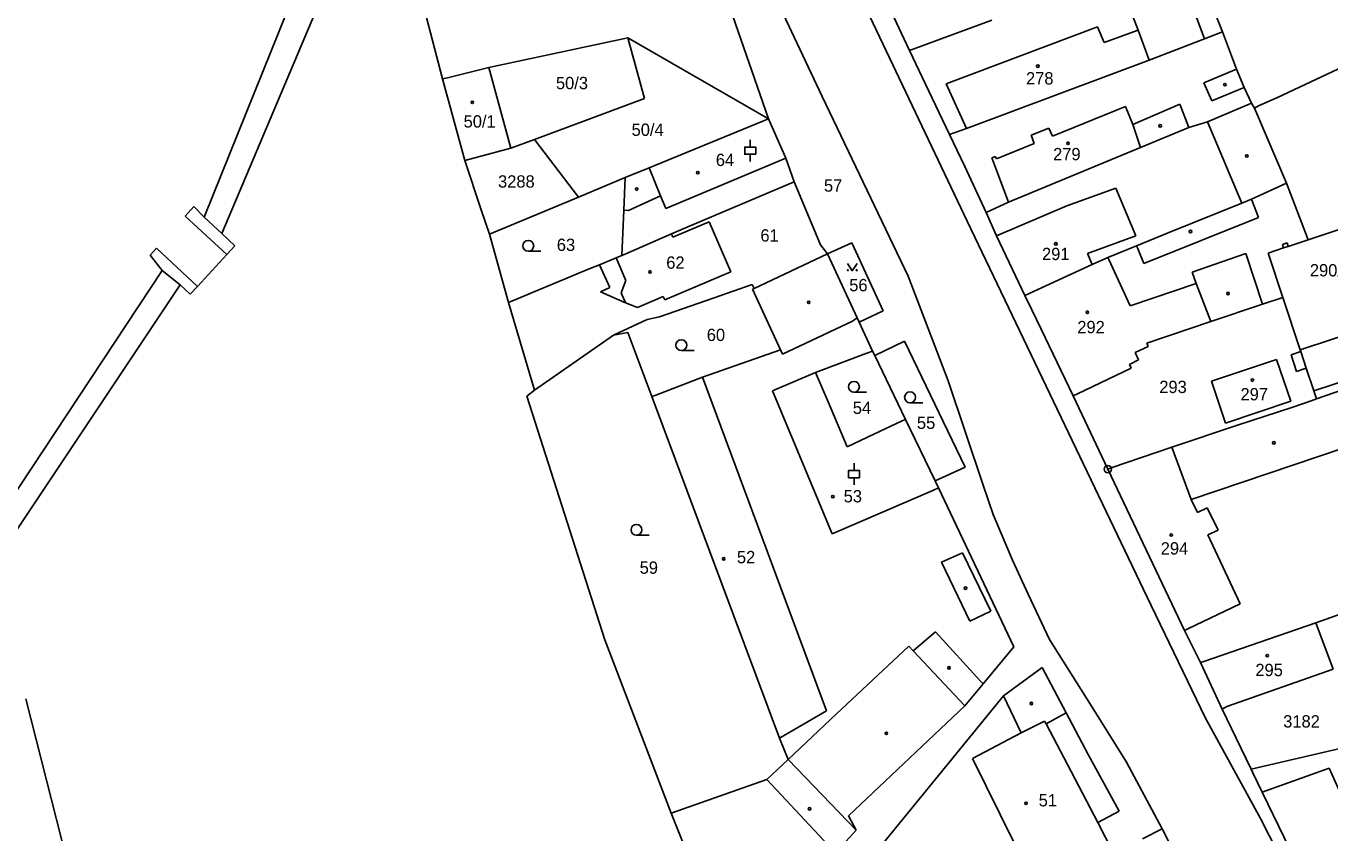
# Model space of a CAD drawing. Extents: x -736345 to -729997, y -1130177 to -1122501.
# Drawn here: x -733843 to -733663.1, y -1126639.6 to -1126528.3 of the extents above; entities that cross this region are included whole.
import ezdxf

# ---------------------------------------------------------------- set-up
doc = ezdxf.new("R2010")
doc.units = 0
for name, color, linetype in [('Vrstva 1', 7, 'Continuous'), ('Vrstva 18', 7, 'Continuous'), ('Vrstva 19', 7, 'Continuous'), ('Vrstva 25', 7, 'Continuous'), ('Vrstva 4', 7, 'Continuous')]:
    doc.layers.add(name, color=color, linetype=linetype)

msp = doc.modelspace()

# ---------------------------------------------------------------- linework, layer by layer
at = {"layer": 'Vrstva 1'}
for points in [[(-733731.42, -1126516.63), (-733713.1, -1126555.17)], [(-733685.1, -1126517.34), (-733680.35, -1126530.03)], [(-733677.89, -1126529.05), (-733682.88, -1126516.53)], [(-733785.51, -1126535.51), (-733789.39, -1126520.69)], [(-733740.8, -1126521.64), (-733733.13, -1126537.99)], [(-733726.49, -1126520.05), (-733721.07, -1126531.61)], [(-733745.84, -1126525.67), (-733740.52, -1126541.04)], [(-733721.07, -1126531.61), (-733709.72, -1126527.43)], [(-733649.04, -1126528.12), (-733670.3, -1126538.13)], [(-733759.93, -1126529.89), (-733779.1, -1126533.95)], [(-733757.61, -1126538.25), (-733759.93, -1126529.89)], [(-733740.52, -1126541.04), (-733759.93, -1126529.89)], [(-733680.35, -1126530.03), (-733688, -1126532.96)], [(-733680.35, -1126530.03), (-733677.89, -1126529.05)], [(-733677.89, -1126529.05), (-733675.94, -1126534.19)], [(-733718.42, -1126537.22), (-733721.07, -1126531.61)], [(-733779.1, -1126533.95), (-733784.81, -1126535.39)], [(-733779.1, -1126533.95), (-733776.08, -1126545.11)], [(-733688, -1126532.96), (-733713.21, -1126542.37)], [(-733675.94, -1126534.19), (-733674.88, -1126536.71)], [(-733784.81, -1126535.39), (-733785.51, -1126535.51)], [(-733785.51, -1126535.51), (-733782.42, -1126546.78)], [(-733733.13, -1126537.99), (-733721.26, -1126562.75)], [(-733715.54, -1126543.2), (-733718.42, -1126537.22)], [(-733674.88, -1126536.71), (-733673.88, -1126538.89)], [(-733772.8, -1126543.89), (-733757.61, -1126538.25)], [(-733673.88, -1126538.89), (-733679.95, -1126541.46)], [(-733673.44, -1126539.59), (-733673.88, -1126538.89)], [(-733672.9, -1126539.26), (-733673.44, -1126539.59)], [(-733673.44, -1126539.59), (-733669.06, -1126549.93)], [(-733670.3, -1126538.13), (-733672.9, -1126539.26)], [(-733756.98, -1126547.8), (-733740.52, -1126541.04)], [(-733740.52, -1126541.04), (-733738.11, -1126546.46)], [(-733679.95, -1126541.46), (-733682.51, -1126542.24)], [(-733713.21, -1126542.37), (-733715.54, -1126543.2)], [(-733713.45, -1126547.64), (-733715.54, -1126543.2)], [(-733682.51, -1126542.24), (-733689.17, -1126545)], [(-733782.42, -1126546.78), (-733776.08, -1126545.11)], [(-733776.08, -1126545.11), (-733772.8, -1126543.89)], [(-733766.76, -1126551.84), (-733772.8, -1126543.89)], [(-733689.17, -1126545), (-733707.42, -1126552.54)], [(-733782.42, -1126546.78), (-733780.15, -1126553.61)], [(-733738.11, -1126546.46), (-733737, -1126549.74)], [(-733760.31, -1126549.16), (-733756.98, -1126547.8)], [(-733710.48, -1126553.96), (-733713.45, -1126547.64)], [(-733766.76, -1126551.84), (-733760.31, -1126549.16)], [(-733760.31, -1126549.16), (-733760.47, -1126553.67)], [(-733751.96, -1126556.08), (-733737, -1126549.74)], [(-733737, -1126549.74), (-733733.33, -1126558.42)], [(-733669.06, -1126549.93), (-733673.87, -1126552.12)], [(-733669.06, -1126549.93), (-733666.06, -1126557.74)], [(-733779.04, -1126556.94), (-733766.76, -1126551.84)], [(-733673.87, -1126552.12), (-733675.22, -1126552.67)], [(-733780.15, -1126553.61), (-733779.04, -1126556.94)], [(-733760.47, -1126553.67), (-733760.76, -1126559.9)], [(-733707.42, -1126552.54), (-733710.48, -1126553.96)], [(-733710.48, -1126553.96), (-733709.04, -1126557.2)], [(-733685.38, -1126556.79), (-733675.22, -1126552.67)], [(-733753.72, -1126557.39), (-733748.7, -1126555.24)], [(-733748.7, -1126555.24), (-733745.7, -1126562.14)], [(-733713.1, -1126555.17), (-733687.72, -1126608.18)], [(-733658.17, -1126555.13), (-733666.06, -1126557.74)], [(-733779.04, -1126556.94), (-733776.4, -1126566.37)], [(-733760.21, -1126559.66), (-733753.91, -1126556.93)], [(-733753.91, -1126556.93), (-733751.96, -1126556.08)], [(-733753.91, -1126556.93), (-733753.72, -1126557.39)], [(-733709.04, -1126557.2), (-733705.15, -1126565.4)], [(-733689.74, -1126558.57), (-733685.38, -1126556.79)], [(-733666.06, -1126557.74), (-733668.8, -1126558.65)], [(-733733.33, -1126558.42), (-733732.36, -1126559.69)], [(-733732.36, -1126559.69), (-733729.04, -1126558.15)], [(-733729.04, -1126558.15), (-733724.69, -1126567.55)], [(-733693.71, -1126560.18), (-733689.74, -1126558.57)], [(-733669.44, -1126558.86), (-733671.56, -1126559.57)], [(-733671.56, -1126559.57), (-733669.54, -1126565.7)], [(-733668.95, -1126558.16), (-733669.6, -1126558.38)], [(-733669.6, -1126558.38), (-733669.44, -1126558.86)], [(-733668.8, -1126558.65), (-733668.95, -1126558.16)], [(-733765.26, -1126561.76), (-733763.84, -1126561.17)], [(-733763.84, -1126561.17), (-733761.87, -1126560.36)], [(-733762.42, -1126564.33), (-733763.84, -1126561.17)], [(-733761.87, -1126560.36), (-733761.56, -1126560.23)], [(-733761.56, -1126560.23), (-733760.76, -1126559.9)], [(-733760.76, -1126559.9), (-733760.21, -1126559.66)], [(-733742.52, -1126564.45), (-733732.36, -1126559.69)], [(-733732.36, -1126559.69), (-733728.28, -1126568.49)], [(-733705.15, -1126565.4), (-733695.84, -1126561.14)], [(-733693.71, -1126560.18), (-733695.84, -1126561.14)], [(-733776.4, -1126566.37), (-733765.26, -1126561.76)], [(-733754.84, -1126566.04), (-733745.7, -1126562.14)], [(-733721.26, -1126562.75), (-733715.75, -1126577.18)], [(-733763.72, -1126564.9), (-733762.42, -1126564.33)], [(-733760.24, -1126566.44), (-733763.72, -1126564.9)], [(-733748, -1126565.74), (-733742.79, -1126563.91)], [(-733742.79, -1126563.91), (-733742.52, -1126564.45)], [(-733742.74, -1126564.57), (-733742.52, -1126564.45)], [(-733738.87, -1126572.91), (-733742.74, -1126564.57)], [(-733776.4, -1126566.37), (-733772.79, -1126578.49)], [(-733758.59, -1126567.1), (-733760.24, -1126566.44)], [(-733758.59, -1126567.1), (-733755.04, -1126565.57)], [(-733755.55, -1126568.38), (-733748, -1126565.74)], [(-733755.04, -1126565.57), (-733754.84, -1126566.04)], [(-733705.15, -1126565.4), (-733704.18, -1126567.42)], [(-733679.48, -1126569), (-733672.35, -1126566.6)], [(-733669.54, -1126565.7), (-733672.35, -1126566.6)], [(-733669.54, -1126565.7), (-733667.16, -1126572.92)], [(-733757.27, -1126568.72), (-733755.55, -1126568.38)], [(-733728.28, -1126568.49), (-733728.01, -1126569.09)], [(-733724.69, -1126567.55), (-733728.01, -1126569.09)], [(-733704.18, -1126567.42), (-733702.91, -1126570.07)], [(-733653.79, -1126568.52), (-733667.16, -1126572.92)], [(-733761.9, -1126570.88), (-733757.27, -1126568.72)], [(-733726.15, -1126573.11), (-733728.01, -1126569.09)], [(-733702.91, -1126570.07), (-733698.49, -1126579.28)], [(-733688.33, -1126571.98), (-733679.48, -1126569)], [(-733772.79, -1126578.49), (-733761.9, -1126570.88)], [(-733761.9, -1126570.88), (-733759.92, -1126570.52)], [(-733759.92, -1126570.52), (-733756.62, -1126579.37)], [(-733721.75, -1126571.72), (-733725.86, -1126573.71)], [(-733713.39, -1126589.09), (-733721.75, -1126571.72)], [(-733688.12, -1126572.45), (-733688.33, -1126571.98)], [(-733749.62, -1126576.71), (-733738.87, -1126572.91)], [(-733734.04, -1126576.05), (-733726.95, -1126573.4)], [(-733726.95, -1126573.4), (-733726.15, -1126573.11)], [(-733726.15, -1126573.11), (-733725.86, -1126573.71)], [(-733725.86, -1126573.71), (-733721.64, -1126582.52)], [(-733689.94, -1126573.3), (-733688.12, -1126572.45)], [(-733689.48, -1126574.3), (-733689.94, -1126573.3)], [(-733667.08, -1126573.16), (-733668.41, -1126573.6)], [(-733668.41, -1126573.6), (-733667.65, -1126575.9)], [(-733667.16, -1126572.92), (-733667.08, -1126573.16)], [(-733697.89, -1126578.99), (-733690.48, -1126575.46)], [(-733690.72, -1126574.93), (-733689.48, -1126574.3)], [(-733690.48, -1126575.46), (-733690.72, -1126574.93)], [(-733679.41, -1126577.26), (-733670.42, -1126574.24)], [(-733670.42, -1126574.24), (-733668.44, -1126579.99)], [(-733667.65, -1126575.9), (-733666.32, -1126575.46)], [(-733666.32, -1126575.46), (-733665.29, -1126578.59)], [(-733651.93, -1126574.22), (-733665.29, -1126578.59)], [(-733756.06, -1126579.16), (-733749.62, -1126576.71)], [(-733739.98, -1126578.59), (-733734.04, -1126576.05)], [(-733734.04, -1126576.05), (-733732.31, -1126580.11)], [(-733715.75, -1126577.18), (-733710.9, -1126591.59)], [(-733677.47, -1126583.02), (-733679.41, -1126577.26)], [(-733772.79, -1126578.49), (-733773.89, -1126579.3)], [(-733773.89, -1126579.3), (-733763.09, -1126612.94)], [(-733756.62, -1126579.37), (-733756.06, -1126579.16)], [(-733739, -1126626.51), (-733756.62, -1126579.37)], [(-733731.75, -1126598.29), (-733739.98, -1126578.59)], [(-733698.49, -1126579.28), (-733697.89, -1126578.99)], [(-733698.49, -1126579.28), (-733693.7, -1126589.38)], [(-733665.29, -1126578.59), (-733664.92, -1126579.68)], [(-733664.92, -1126579.68), (-733658.94, -1126577.63)], [(-733732.31, -1126580.11), (-733729.67, -1126586.28)], [(-733668.44, -1126579.99), (-733677.47, -1126583.02)], [(-733668.18, -1126580.81), (-733675.81, -1126583.3)], [(-733665.62, -1126579.95), (-733668.18, -1126580.81)], [(-733664.92, -1126579.68), (-733665.62, -1126579.95)], [(-733726, -1126584.56), (-733722.09, -1126582.73)], [(-733722.09, -1126582.73), (-733721.64, -1126582.52)], [(-733721.64, -1126582.52), (-733717.54, -1126590.99)], [(-733729.67, -1126586.28), (-733726, -1126584.56)], [(-733675.81, -1126583.3), (-733684.87, -1126586.34)], [(-733684.87, -1126586.34), (-733693.09, -1126589.17)], [(-733717.54, -1126590.99), (-733713.39, -1126589.09)], [(-733693.7, -1126589.38), (-733693.09, -1126589.17)], [(-733683.14, -1126611.63), (-733693.7, -1126589.38)], [(-733717.84, -1126592.3), (-733717.08, -1126591.97)], [(-733717.08, -1126591.97), (-733717.54, -1126590.99)], [(-733717.08, -1126591.97), (-733706.69, -1126613.9)], [(-733710.9, -1126591.59), (-733709.5, -1126595.62)], [(-733717.84, -1126592.3), (-733731.75, -1126598.29)], [(-733709.5, -1126595.62), (-733706.83, -1126601.94)], [(-733706.83, -1126601.94), (-733704.67, -1126606.63)], [(-733649.94, -1126605.24), (-733665.01, -1126610.6)], [(-733704.67, -1126606.63), (-733701.75, -1126612.86)], [(-733687.72, -1126608.18), (-733680.22, -1126623.75)], [(-733680.93, -1126616.06), (-733683.14, -1126611.63)], [(-733665.01, -1126610.6), (-733680.45, -1126615.89)], [(-733665.01, -1126610.6), (-733662.61, -1126616.99)], [(-733763.09, -1126612.94), (-733753.94, -1126636.85)], [(-733701.75, -1126612.86), (-733696.09, -1126621.83)], [(-733706.69, -1126613.9), (-733710.92, -1126618.99)], [(-733708.1, -1126620.64), (-733702.76, -1126616.75)], [(-733699.46, -1126623.01), (-733702.76, -1126616.75)], [(-733680.45, -1126615.89), (-733680.93, -1126616.06)], [(-733680.93, -1126616.06), (-733677.9, -1126622.47)], [(-733662.61, -1126616.99), (-733677.3, -1126622.13)], [(-733717.5, -1126632.15), (-733708.1, -1126620.64)], [(-733710.92, -1126618.99), (-733713.42, -1126622.03)], [(-733823.88, -1126696.34), (-733843.01, -1126621.05)], [(-733713.42, -1126622.03), (-733729.5, -1126637.19)], [(-733691.13, -1126629.82), (-733696.09, -1126621.83)], [(-733677.3, -1126622.13), (-733677.9, -1126622.47)], [(-733677.9, -1126622.47), (-733676.01, -1126626.49)], [(-733699.46, -1126623.01), (-733696.4, -1126628.72)], [(-733680.22, -1126623.75), (-733672.62, -1126637.59)], [(-733737.82, -1126629.44), (-733739, -1126626.51)], [(-733676.01, -1126626.49), (-733673.91, -1126630.78)], [(-733658.87, -1126627.26), (-733673.91, -1126630.78)], [(-733740.75, -1126632.19), (-733737.82, -1126629.44)], [(-733692.12, -1126636.56), (-733696.4, -1126628.72)], [(-733691.13, -1126629.82), (-733686.21, -1126638.98)], [(-733673.91, -1126630.78), (-733673.67, -1126631.27)], [(-733673.67, -1126631.27), (-733672.38, -1126633.95)], [(-733753.94, -1126636.85), (-733740.75, -1126632.19)], [(-733740.75, -1126632.19), (-733731.57, -1126642.03)], [(-733726.5, -1126643.18), (-733717.5, -1126632.15)], [(-733672.38, -1126633.95), (-733665.5, -1126648.15)], [(-733745.44, -1126658.12), (-733753.94, -1126636.85)], [(-733695.1, -1126638.12), (-733692.12, -1126636.56)], [(-733729.5, -1126637.19), (-733728.43, -1126639.17)], [(-733692.99, -1126642.16), (-733695.1, -1126638.12)], [(-733672.62, -1126637.59), (-733664.04, -1126654.46)], [(-733728.43, -1126639.17), (-733731.26, -1126642.3)], [(-733688.91, -1126640.37), (-733686.21, -1126638.98)], [(-733686.21, -1126638.98), (-733681.32, -1126648.5)]]:
    msp.add_lwpolyline(points, dxfattribs=at)
at = {"layer": 'Vrstva 25'}
for points in [[(-733742.29, -1126545.94), (-733743.79, -1126545.94), (-733743.79, -1126544.94), (-733742.29, -1126544.94), (-733742.29, -1126545.94)], [(-733743.04, -1126544.94), (-733743.04, -1126543.94)], [(-733743.04, -1126546.94), (-733743.04, -1126545.94)], [(-733773.67, -1126559.32), (-733771.92, -1126559.32)], [(-733729.63, -1126560.994), (-733728.96, -1126562), (-733728.289, -1126560.994)], [(-733752.55, -1126573.02), (-733750.8, -1126573.02)], [(-733728.73, -1126578.77), (-733726.98, -1126578.77)], [(-733720.99, -1126580.22), (-733719.24, -1126580.22)], [(-733727.97, -1126590.56), (-733729.47, -1126590.56), (-733729.47, -1126589.56), (-733727.97, -1126589.56), (-733727.97, -1126590.56)], [(-733728.72, -1126589.56), (-733728.72, -1126588.56)], [(-733728.72, -1126591.56), (-733728.72, -1126590.56)], [(-733758.74, -1126598.5), (-733756.99, -1126598.5)]]:
    msp.add_lwpolyline(points, dxfattribs=at)
for centre, radius in [((-733703.36, -1126533.79), 0.175), ((-733677.54, -1126536.34), 0.175), ((-733781.39, -1126538.78), 0.175), ((-733686.48, -1126542.01), 0.175), ((-733699.2, -1126544.42), 0.175), ((-733674.51, -1126546.18), 0.175), ((-733750.27, -1126548.48), 0.175), ((-733758.7, -1126550.74), 0.175), ((-733682.29, -1126556.6), 0.175), ((-733773.67, -1126558.57), 0.75), ((-733700.88, -1126558.3), 0.175), ((-733756.87, -1126562.17), 0.175), ((-733729.563, -1126561.933), 0.067), ((-733728.356, -1126561.933), 0.067), ((-733677.11, -1126565.14), 0.175), ((-733734.97, -1126566.36), 0.175), ((-733696.52, -1126567.73), 0.175), ((-733752.55, -1126572.27), 0.75), ((-733728.73, -1126578.02), 0.75), ((-733673.75, -1126577.09), 0.175), ((-733720.99, -1126579.47), 0.75), ((-733670.8, -1126585.74), 0.175), ((-733693.7, -1126589.38), 0.5), ((-733693.7, -1126589.38), 0.032), ((-733731.65, -1126593.18), 0.175), ((-733758.74, -1126597.75), 0.75), ((-733684.95, -1126598.46), 0.175), ((-733746.7, -1126601.75), 0.175), ((-733713.34, -1126605.8), 0.175), ((-733671.7, -1126615.1), 0.175), ((-733715.61, -1126616.78), 0.175), ((-733704.25, -1126621.71), 0.175), ((-733724.26, -1126625.82), 0.175), ((-733734.85, -1126636.23), 0.175), ((-733704.98, -1126635.48), 0.175)]:
    msp.add_circle(centre, radius, dxfattribs=at)
at = {"layer": 'Vrstva 4'}
for points in [[(-733818.4, -1126554.6), (-733805.63, -1126522.96)], [(-733802.11, -1126524.09), (-733815.96, -1126556.86)], [(-733691.3, -1126524.14), (-733689.52, -1126528.8)], [(-733695.12, -1126528.37), (-733716, -1126536.23)], [(-733694.21, -1126530.51), (-733695.12, -1126528.37)], [(-733689.52, -1126528.8), (-733694.21, -1126530.51)], [(-733689.52, -1126528.8), (-733688, -1126532.96)], [(-733675.94, -1126534.19), (-733680.43, -1126536.08)], [(-733680.43, -1126536.08), (-733679.33, -1126538.58)], [(-733716, -1126536.23), (-733713.21, -1126542.37)], [(-733679.33, -1126538.58), (-733674.88, -1126536.71)], [(-733701.35, -1126543.44), (-733691.27, -1126539.35)], [(-733691.27, -1126539.35), (-733690.26, -1126541.83)], [(-733690.26, -1126541.83), (-733683.77, -1126539.03)], [(-733683.77, -1126539.03), (-733682.51, -1126542.24)], [(-733679.95, -1126541.46), (-733675.22, -1126552.67)], [(-733704.27, -1126543.32), (-733701.84, -1126542.34)], [(-733703.85, -1126544.46), (-733704.27, -1126543.32)], [(-733701.84, -1126542.34), (-733701.35, -1126543.44)], [(-733690.26, -1126541.83), (-733689.17, -1126545)], [(-733709.06, -1126546.57), (-733703.85, -1126544.46)], [(-733754.67, -1126553.41), (-733738.11, -1126546.46)], [(-733709.7, -1126546.43), (-733709.25, -1126546.24)], [(-733707.42, -1126552.54), (-733709.7, -1126546.43)], [(-733709.25, -1126546.24), (-733709.06, -1126546.57)], [(-733755.44, -1126551.67), (-733756.98, -1126547.8)], [(-733699.35, -1126553.07), (-733692.6, -1126550.6)], [(-733692.6, -1126550.6), (-733689.85, -1126557.19)], [(-733759.86, -1126553.69), (-733755.44, -1126551.67)], [(-733755.44, -1126551.67), (-733754.67, -1126553.41)], [(-733672.91, -1126554.66), (-733673.87, -1126552.12)], [(-733821.01, -1126554.48), (-733819.8, -1126553.14)], [(-733819.8, -1126553.14), (-733818.4, -1126554.6)], [(-733759.86, -1126553.69), (-733760.47, -1126553.67)], [(-733709.04, -1126557.2), (-733699.35, -1126553.07)], [(-733815.28, -1126559.78), (-733821.01, -1126554.48)], [(-733818.4, -1126554.6), (-733815.96, -1126556.86)], [(-733688.75, -1126560.99), (-733672.91, -1126554.66)], [(-733815.96, -1126556.86), (-733814.15, -1126558.55)], [(-733689.85, -1126557.19), (-733696.51, -1126559.63)], [(-733824.95, -1126558.87), (-733825.85, -1126559.88)], [(-733819.33, -1126564.16), (-733824.95, -1126558.87)], [(-733814.15, -1126558.55), (-733815.28, -1126559.78)], [(-733689.74, -1126558.57), (-733689.62, -1126558.86)], [(-733689.62, -1126558.86), (-733688.75, -1126560.99)], [(-733669.44, -1126558.86), (-733668.8, -1126558.65)], [(-733825.85, -1126559.88), (-733824.17, -1126561.96)], [(-733815.28, -1126559.78), (-733819.33, -1126564.16)], [(-733761.56, -1126560.23), (-733760.21, -1126563.36)], [(-733696.51, -1126559.63), (-733695.84, -1126561.14)], [(-733693.58, -1126560.47), (-733693.71, -1126560.18)], [(-733690.63, -1126566.84), (-733693.58, -1126560.47)], [(-733682.06, -1126562.19), (-733674.65, -1126559.61)], [(-733674.65, -1126559.61), (-733672.35, -1126566.6)], [(-733824.17, -1126561.96), (-733850.46, -1126601.66)], [(-733824.17, -1126561.96), (-733821.69, -1126563.93)], [(-733681.53, -1126563.75), (-733682.06, -1126562.19)], [(-733821.69, -1126563.93), (-733848.7, -1126604.38)], [(-733821.69, -1126563.93), (-733820.31, -1126565.22)], [(-733820.31, -1126565.22), (-733819.33, -1126564.16)], [(-733760.21, -1126563.36), (-733760.84, -1126565.05)], [(-733681.53, -1126563.75), (-733690.63, -1126566.84)], [(-733681.53, -1126563.75), (-733679.48, -1126569)], [(-733760.84, -1126565.05), (-733760.24, -1126566.44)], [(-733728.95, -1126568.98), (-733728.28, -1126568.49)], [(-733738.59, -1126573.52), (-733728.95, -1126568.98)], [(-733738.87, -1126572.91), (-733738.59, -1126573.52)], [(-733667.08, -1126573.16), (-733666.32, -1126575.46)], [(-733732.53, -1126622.74), (-733749.62, -1126576.71)], [(-733654.14, -1126584.09), (-733682.22, -1126593.58)], [(-733682.22, -1126593.58), (-733684.87, -1126586.34)], [(-733682.22, -1126593.58), (-733681.33, -1126595.37)], [(-733681.33, -1126595.37), (-733680, -1126594.71)], [(-733680, -1126594.71), (-733678.48, -1126597.78)], [(-733678.48, -1126597.78), (-733679.92, -1126598.44)], [(-733679.92, -1126598.44), (-733675.44, -1126607.96)], [(-733716.67, -1126602.21), (-733713.76, -1126600.92)], [(-733713.76, -1126600.92), (-733709.86, -1126608.99)], [(-733712.72, -1126610.37), (-733716.67, -1126602.21)], [(-733675.44, -1126607.96), (-733682.68, -1126611.41)], [(-733709.86, -1126608.99), (-733712.72, -1126610.37)], [(-733682.68, -1126611.41), (-733683.14, -1126611.63)], [(-733720.55, -1126614.46), (-733717.5, -1126611.81)], [(-733717.5, -1126611.81), (-733711.29, -1126618.64)], [(-733731.14, -1126623.11), (-733721.14, -1126613.79)], [(-733721.14, -1126613.79), (-733720.55, -1126614.46)], [(-733713.42, -1126622.03), (-733720.55, -1126614.46)], [(-733711.29, -1126618.64), (-733710.92, -1126618.99)], [(-733708.1, -1126620.64), (-733705.67, -1126625.77)], [(-733739, -1126626.51), (-733732.53, -1126622.74)], [(-733737.82, -1126629.44), (-733731.14, -1126623.11)], [(-733705.67, -1126625.77), (-733702.42, -1126624.14)], [(-733702.42, -1126624.14), (-733702.23, -1126624.5)], [(-733702.23, -1126624.5), (-733699.46, -1126623.01)], [(-733712.36, -1126629.29), (-733705.67, -1126625.77)], [(-733699.25, -1126630.14), (-733702.23, -1126624.5)], [(-733737.82, -1126629.44), (-733728.43, -1126639.17)], [(-733706.68, -1126640.82), (-733712.36, -1126629.29)], [(-733699.25, -1126630.14), (-733695.1, -1126638.12)], [(-733672.38, -1126633.95), (-733663.14, -1126630.64)], [(-733663.14, -1126630.64), (-733661.08, -1126635.24)]]:
    msp.add_lwpolyline(points, dxfattribs=at)

# ---------------------------------------------------------------- texts
at = {"layer": 'Vrstva 18'}
for s, p in [('50/3', (-733769.85, -1126536.96)), ('50/4', (-733759.41, -1126543.4)), ('3288', (-733777.84, -1126550.54)), ('57', (-733732.87, -1126551.1)), ('63', (-733769.73, -1126559.28)), ('61', (-733741.64, -1126557.98)), ('56', (-733729.38, -1126564.84)), ('60', (-733749.04, -1126571.7)), ('293', (-733686.6, -1126578.88)), ('54', (-733728.89, -1126581.76)), ('55', (-733720.04, -1126583.83)), ('59', (-733758.3, -1126603.81)), ('3182', (-733669.5, -1126625.02))]:
    msp.add_text(s, height=1.7, dxfattribs=at).set_placement(p)
at = {"layer": 'Vrstva 19'}
for s, p in [('278', (-733704.99, -1126536.31)), ('50/1', (-733782.59, -1126542.25)), ('279', (-733701.25, -1126546.77)), ('64', (-733747.79, -1126547.56)), ('291', (-733702.78, -1126560.54)), ('62', (-733754.63, -1126561.73)), ('290/8', (-733665.82, -1126562.79)), ('292', (-733697.91, -1126570.63)), ('297', (-733675.39, -1126579.89)), ('53', (-733730.15, -1126593.96)), ('52', (-733744.88, -1126602.36)), ('294', (-733686.4, -1126601.16)), ('295', (-733673.34, -1126617.93)), ('51', (-733703.24, -1126635.9))]:
    msp.add_text(s, height=1.7, dxfattribs=at).set_placement(p)

doc.saveas('drawing.dxf')
